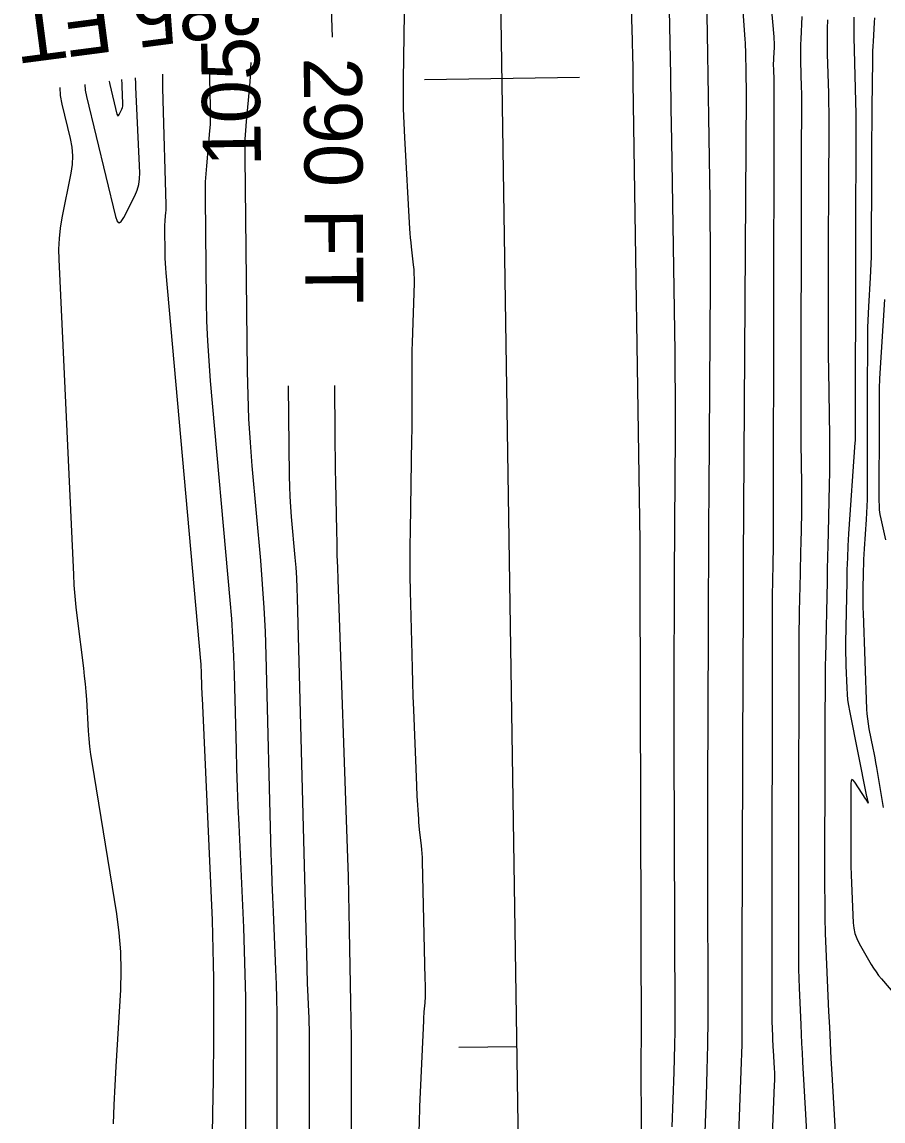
# Model space of a CAD drawing. Extents: x 1768942 to 1774819, y 723037 to 732099.
# Drawn here: x 1770772.9 to 1770861.8, y 724629.5 to 724743.1 of the extents above; entities that cross this region are included whole.
import ezdxf

# ---------------------------------------------------------------- set-up
doc = ezdxf.new("R2010")
doc.units = 0
for name, color, linetype in [('R_Contour Annot', 7, 'Continuous'), ('R_Contours', 7, 'Continuous'), ('R_Horz Alg', 7, 'Continuous'), ('R_Horz Alg Annot', 7, 'Continuous')]:
    doc.layers.add(name, color=color, linetype=linetype)

msp = doc.modelspace()

# ---------------------------------------------------------------- linework, layer by layer
at = {"layer": 'R_Contours'}
for points in [[(1770844.77, 724779.86), (1770847.51, 724741.26), (1770847.54, 724740.9), (1770847.56, 724740.53), (1770847.57, 724740.16), (1770847.58, 724739.79), (1770847.61, 724737.96), (1770847.62, 724737.76), (1770847.62, 724737.56), (1770847.62, 724737.37), (1770847.63, 724737.17), (1770847.64, 724736.38), (1770847.64, 724736.18), (1770847.64, 724735.98), (1770847.64, 724735.79), (1770847.64, 724735.59), (1770847.41, 724698.11), (1770847.38, 724692.78), (1770847.35, 724687.45), (1770847.33, 724682.11), (1770847.31, 724676.78), (1770847.2, 724646.63), (1770847.2, 724645.71), (1770847.2, 724644.79), (1770847.2, 724643.87), (1770847.2, 724642.95), (1770847.21, 724639.28), (1770847.21, 724638.36), (1770847.2, 724637.44), (1770847.18, 724636.53), (1770847.15, 724635.61), (1770846.14, 724608.57)], [(1770849.86, 724615.06), (1770850.59, 724633.3), (1770850.61, 724633.72), (1770850.61, 724634.14), (1770850.6, 724634.55), (1770850.58, 724634.97), (1770850.47, 724636.88), (1770850.45, 724637.18), (1770850.44, 724637.49), (1770850.42, 724637.79), (1770850.41, 724638.1), (1770850.36, 724639.32), (1770850.34, 724639.62), (1770850.34, 724639.93), (1770850.33, 724640.23), (1770850.33, 724640.54), (1770850.34, 724642.64), (1770850.34, 724643.1), (1770850.34, 724643.55), (1770850.34, 724644), (1770850.34, 724644.45), (1770850.38, 724684.06), (1770850.38, 724684.4), (1770850.39, 724684.75), (1770850.39, 724685.1), (1770850.4, 724685.45), (1770850.43, 724686.95), (1770850.44, 724687.24), (1770850.44, 724687.53), (1770850.45, 724687.82), (1770850.46, 724688.12), (1770850.48, 724689.29), (1770850.49, 724689.58), (1770850.49, 724689.87), (1770850.49, 724690.16), (1770850.49, 724690.46), (1770850.47, 724692.05), (1770850.46, 724692.41), (1770850.46, 724692.77), (1770850.46, 724693.13), (1770850.46, 724693.49), (1770850.53, 724732.48), (1770850.53, 724732.87), (1770850.53, 724733.26), (1770850.53, 724733.65), (1770850.54, 724734.04), (1770850.55, 724735.78), (1770850.55, 724736.08), (1770850.54, 724736.38), (1770850.54, 724736.68), (1770850.53, 724736.98), (1770850.5, 724738.24), (1770850.49, 724738.52), (1770850.49, 724738.79), (1770850.5, 724739.06), (1770850.51, 724739.34), (1770850.56, 724740.43), (1770850.56, 724740.7), (1770850.56, 724740.97), (1770850.55, 724741.24), (1770850.53, 724741.52), (1770847.14, 724779.89)], [(1770843.13, 724620.91), (1770843.55, 724632.15), (1770843.64, 724634.79), (1770843.69, 724637.42), (1770843.73, 724640.06), (1770843.73, 724642.69), (1770843.7, 724653.23), (1770843.69, 724655.86), (1770843.69, 724658.5), (1770843.69, 724661.13), (1770843.7, 724663.77), (1770843.76, 724680.19), (1770843.77, 724683.81), (1770843.79, 724687.42), (1770843.81, 724691.04), (1770843.83, 724694.65), (1770843.96, 724716.03), (1770843.97, 724718.18), (1770843.97, 724720.33), (1770843.95, 724722.49), (1770843.92, 724724.64), (1770843.79, 724733.25), (1770843.76, 724735.41), (1770843.73, 724737.56), (1770843.69, 724739.71), (1770843.65, 724741.86), (1770843.17, 724767.24)], [(1770835.26, 724760.92), (1770835.87, 724741.19), (1770835.88, 724740.82), (1770835.89, 724740.46), (1770835.9, 724740.1), (1770835.91, 724739.73), (1770835.94, 724738.27), (1770835.94, 724737.91), (1770835.95, 724737.55), (1770835.95, 724737.18), (1770835.96, 724736.82), (1770836.67, 724689.45), (1770836.67, 724689.24), (1770836.68, 724689.03), (1770836.68, 724688.82), (1770836.68, 724688.62), (1770836.67, 724687.74), (1770836.67, 724687.56), (1770836.67, 724687.37), (1770836.67, 724687.19), (1770836.67, 724687.01), (1770836.66, 724686.28), (1770836.66, 724686.1), (1770836.66, 724685.91), (1770836.66, 724685.73), (1770836.66, 724685.55), (1770836.81, 724637.51), (1770836.81, 724637.44), (1770836.81, 724637.37), (1770836.81, 724637.3), (1770836.8, 724637.23), (1770836.79, 724636.96), (1770836.79, 724636.89), (1770836.79, 724636.82), (1770836.79, 724636.75), (1770836.79, 724636.68), (1770836.95, 724590.56)], [(1770804.96, 724741.5), (1770804.71, 724748.47)], [(1770839.71, 724744.32), (1770839.77, 724740.93), (1770839.83, 724737.55), (1770839.89, 724734.17), (1770839.94, 724730.79), (1770840.27, 724709), (1770840.3, 724706.84), (1770840.31, 724704.68), (1770840.31, 724702.52), (1770840.31, 724700.36), (1770840.25, 724691.19), (1770840.24, 724689.3), (1770840.23, 724687.4), (1770840.22, 724685.5), (1770840.21, 724683.6), (1770840.19, 724676), (1770840.18, 724674.1), (1770840.18, 724672.21), (1770840.18, 724670.31), (1770840.18, 724668.41), (1770840.27, 724640.22), (1770840.27, 724638.81), (1770840.25, 724637.4), (1770840.22, 724635.99), (1770840.17, 724634.58), (1770839.96, 724628.94)], [(1770813.9, 724628.27), (1770813.93, 724629.66), (1770813.94, 724630), (1770813.95, 724630.35), (1770813.96, 724630.7), (1770813.97, 724631.04), (1770814.36, 724639.91), (1770814.37, 724640.14), (1770814.39, 724640.37), (1770814.4, 724640.6), (1770814.42, 724640.82), (1770814.5, 724641.77), (1770814.52, 724641.98), (1770814.53, 724642.18), (1770814.53, 724642.39), (1770814.53, 724642.59), (1770814.53, 724643.41), (1770814.53, 724643.61), (1770814.53, 724643.82), (1770814.52, 724644.02), (1770814.52, 724644.23), (1770814.24, 724656.37), (1770814.23, 724656.78), (1770814.21, 724657.18), (1770814.17, 724657.58), (1770814.13, 724657.98), (1770813.94, 724659.64), (1770813.9, 724660.02), (1770813.87, 724660.4), (1770813.84, 724660.78), (1770813.81, 724661.16), (1770813.71, 724662.68), (1770813.69, 724663.07), (1770813.67, 724663.45), (1770813.65, 724663.83), (1770813.64, 724664.21), (1770813.34, 724672.01), (1770813.28, 724673.44), (1770813.24, 724674.87), (1770813.19, 724676.29), (1770813.16, 724677.72), (1770813, 724684.27), (1770812.97, 724685.83), (1770812.96, 724687.4), (1770812.96, 724688.97), (1770812.98, 724690.54), (1770813.15, 724700.05), (1770813.16, 724700.87), (1770813.17, 724701.7), (1770813.17, 724702.52), (1770813.17, 724703.35), (1770813.16, 724706.65), (1770813.16, 724707.48), (1770813.17, 724708.3), (1770813.18, 724709.13), (1770813.2, 724709.96), (1770813.4, 724716.09), (1770813.4, 724716.56), (1770813.39, 724717.03), (1770813.36, 724717.49), (1770813.32, 724717.96), (1770813.1, 724719.83), (1770813.05, 724720.29), (1770813, 724720.76), (1770812.97, 724721.23), (1770812.94, 724721.7), (1770812.4, 724731.13), (1770812.33, 724732.61), (1770812.29, 724734.1), (1770812.27, 724735.58), (1770812.28, 724737.07), (1770812.37, 724743.93)], [(1770853.39, 724743.61), (1770853.28, 724741.3), (1770853.26, 724740.73), (1770853.25, 724740.15), (1770853.25, 724739.57), (1770853.26, 724739), (1770853.34, 724736.34), (1770853.35, 724735.7), (1770853.36, 724735.07), (1770853.37, 724734.43), (1770853.36, 724733.8), (1770853.34, 724730.13), (1770853.34, 724729.3), (1770853.34, 724728.48), (1770853.33, 724727.66), (1770853.33, 724726.83), (1770853.29, 724703.38), (1770853.29, 724702.43), (1770853.29, 724701.47), (1770853.3, 724700.51), (1770853.31, 724699.56), (1770853.37, 724695.37), (1770853.38, 724694.6), (1770853.38, 724693.83), (1770853.37, 724693.06), (1770853.36, 724692.28), (1770853.29, 724689.2), (1770853.27, 724688.43), (1770853.25, 724687.66), (1770853.23, 724686.88), (1770853.22, 724686.11), (1770853.13, 724682.16), (1770853.11, 724681.24), (1770853.1, 724680.32), (1770853.09, 724679.41), (1770853.09, 724678.49), (1770853.07, 724659.5), (1770853.07, 724658.07), (1770853.06, 724656.65), (1770853.06, 724655.22), (1770853.06, 724653.79), (1770853.04, 724647.16), (1770853.04, 724646.2), (1770853.06, 724645.24), (1770853.08, 724644.28), (1770853.12, 724643.32), (1770853.29, 724639.48), (1770853.33, 724638.52), (1770853.38, 724637.56), (1770853.43, 724636.6), (1770853.48, 724635.64), (1770853.82, 724629.63), (1770853.88, 724628.31)], [(1770856.06, 724743.27), (1770856.03, 724742.39), (1770856.01, 724741.51), (1770856.01, 724740.63), (1770856.03, 724739.75), (1770856.14, 724735.69), (1770856.16, 724734.72), (1770856.18, 724733.75), (1770856.18, 724732.78), (1770856.18, 724731.81), (1770856.15, 724726.21), (1770856.14, 724724.95), (1770856.14, 724723.7), (1770856.13, 724722.44), (1770856.13, 724721.18), (1770856.12, 724713.27), (1770856.12, 724711.72), (1770856.12, 724710.17), (1770856.13, 724708.62), (1770856.15, 724707.07), (1770856.25, 724700.28), (1770856.26, 724699.03), (1770856.26, 724697.78), (1770856.25, 724696.53), (1770856.23, 724695.28), (1770856.11, 724690.28), (1770856.08, 724689.03), (1770856.06, 724687.78), (1770856.03, 724686.53), (1770856, 724685.28), (1770855.83, 724677.43), (1770855.82, 724676.67), (1770855.81, 724675.9), (1770855.8, 724675.13), (1770855.8, 724674.36), (1770855.79, 724671.28), (1770855.79, 724670.51), (1770855.79, 724669.75), (1770855.79, 724668.98), (1770855.79, 724668.21), (1770855.75, 724653.78), (1770855.76, 724652.17), (1770855.78, 724650.55), (1770855.82, 724648.93), (1770855.88, 724647.32), (1770856.16, 724640.86), (1770856.24, 724639.24), (1770856.31, 724637.62), (1770856.4, 724636.01), (1770856.49, 724634.4), (1770857.17, 724622.43)], [(1770858.77, 724743.56), (1770858.76, 724742.87), (1770858.76, 724742.19), (1770858.77, 724741.5), (1770858.99, 724733.53), (1770858.99, 724733.43), (1770858.99, 724733.32), (1770858.99, 724733.21), (1770858.99, 724733.11), (1770858.98, 724732.68), (1770858.98, 724732.57), (1770858.98, 724732.47), (1770858.98, 724732.36), (1770858.98, 724732.25), (1770858.94, 724720.48), (1770858.94, 724720.33), (1770858.94, 724720.17), (1770858.94, 724720.01), (1770858.94, 724719.86), (1770858.94, 724718.92), (1770858.94, 724718.88), (1770858.94, 724718.86), (1770858.94, 724718.65), (1770858.94, 724718.61), (1770858.94, 724718.58), (1770858.94, 724718.54), (1770858.94, 724718.5), (1770858.91, 724701.53), (1770858.91, 724701.37), (1770858.91, 724701.21), (1770858.91, 724701.06), (1770858.91, 724700.9), (1770858.91, 724700.27), (1770858.9, 724700.11), (1770858.9, 724699.95), (1770858.89, 724699.8), (1770858.88, 724699.64), (1770858.23, 724690.18), (1770858.16, 724688.94), (1770858.1, 724687.7), (1770858.05, 724686.47), (1770858.03, 724685.23), (1770857.92, 724678.98), (1770857.92, 724678.38), (1770857.92, 724677.79), (1770857.93, 724677.2), (1770857.95, 724676.61), (1770858.04, 724674.24), (1770858.07, 724673.65), (1770858.13, 724673.06), (1770858.21, 724672.48), (1770858.31, 724671.9), (1770860.09, 724663.06), (1770860.1, 724663.04), (1770860.1, 724663.02), (1770860.1, 724663), (1770860.11, 724662.99), (1770860.12, 724662.91), (1770860.12, 724662.89), (1770860.13, 724662.88), (1770860.13, 724662.86), (1770860.13, 724662.84), (1770860.24, 724662.42), (1770860.25, 724662.38), (1770860.25, 724662.37), (1770860.24, 724662.38), (1770860.22, 724662.42), (1770860.11, 724662.61), (1770860.09, 724662.66), (1770860.06, 724662.71), (1770860.03, 724662.75), (1770860, 724662.8), (1770858.87, 724664.53), (1770858.7, 724664.75), (1770858.57, 724664.81), (1770858.5, 724664.69), (1770858.47, 724664.41), (1770858.45, 724657.6), (1770858.46, 724656.73), (1770858.47, 724655.86), (1770858.49, 724654.99), (1770858.53, 724654.12), (1770858.7, 724650.03), (1770858.76, 724649.47), (1770858.88, 724648.92), (1770859.07, 724648.4), (1770859.32, 724647.89), (1770860.57, 724645.71), (1770860.81, 724645.32), (1770861.06, 724644.94), (1770861.33, 724644.57), (1770861.62, 724644.22), (1770862.99, 724642.61)], [(1770860.9, 724743.49), (1770860.88, 724743), (1770860.76, 724741.04), (1770860.73, 724740.55), (1770860.71, 724740.06), (1770860.7, 724739.56), (1770860.69, 724739.07), (1770860.63, 724734.21), (1770860.61, 724733.24), (1770860.61, 724732.27), (1770860.6, 724731.29), (1770860.6, 724730.32), (1770860.58, 724725.31), (1770860.58, 724724.58), (1770860.58, 724723.86), (1770860.57, 724723.14), (1770860.57, 724722.42), (1770860.56, 724719.54), (1770860.55, 724718.81), (1770860.53, 724718.09), (1770860.5, 724717.37), (1770860.46, 724716.65), (1770860.27, 724713.69), (1770860.23, 724712.96), (1770860.2, 724712.23), (1770860.18, 724711.49), (1770860.18, 724710.76), (1770860.16, 724704.22), (1770860.16, 724703.1), (1770860.16, 724701.99), (1770860.16, 724700.87), (1770860.15, 724699.75), (1770860.14, 724694.41), (1770860.13, 724693.73), (1770860.11, 724693.04), (1770860.08, 724692.35), (1770860.04, 724691.67), (1770859.83, 724688.66), (1770859.8, 724688.1), (1770859.77, 724687.55), (1770859.75, 724686.99), (1770859.74, 724686.44), (1770859.7, 724684.22), (1770859.7, 724683.66), (1770859.7, 724683.11), (1770859.71, 724682.55), (1770859.73, 724682), (1770860.09, 724672.1), (1770860.12, 724671.59), (1770860.17, 724671.08), (1770860.24, 724670.58), (1770860.33, 724670.07), (1770860.73, 724668.07), (1770860.83, 724667.57), (1770860.93, 724667.06), (1770861.02, 724666.56), (1770861.11, 724666.06), (1770861.8, 724661.94)], [(1770799.24, 724627.33), (1770799.24, 724639.21), (1770799.23, 724640.7), (1770799.21, 724642.19), (1770799.16, 724643.69), (1770799.1, 724645.18), (1770798.84, 724651.15), (1770798.77, 724652.65), (1770798.72, 724654.14), (1770798.67, 724655.63), (1770798.62, 724657.13), (1770798.1, 724677.67), (1770798.02, 724680.12), (1770797.89, 724682.56), (1770797.73, 724685.01), (1770797.54, 724687.44), (1770796.66, 724697.2), (1770796.47, 724699.64), (1770796.32, 724702.08), (1770796.22, 724704.52), (1770796.17, 724706.97), (1770795.92, 724729.08), (1770795.92, 724730.01), (1770795.94, 724730.94), (1770795.99, 724731.86), (1770796.07, 724732.79), (1770796.41, 724736.48), (1770796.48, 724737.41), (1770796.52, 724738.33), (1770796.54, 724738.86)], [(1770792.38, 724618.38), (1770792.63, 724632.17), (1770792.65, 724633.68), (1770792.67, 724635.19), (1770792.68, 724636.7), (1770792.68, 724638.21), (1770792.68, 724644.25), (1770792.67, 724645.75), (1770792.64, 724647.26), (1770792.6, 724648.77), (1770792.54, 724650.28), (1770791.51, 724673.23), (1770791.49, 724673.54), (1770791.48, 724673.86), (1770791.47, 724674.18), (1770791.46, 724674.5), (1770791.43, 724675.77), (1770791.42, 724676.09), (1770791.4, 724676.41), (1770791.38, 724676.73), (1770791.36, 724677.05), (1770787.77, 724717.14), (1770787.73, 724717.64), (1770787.7, 724718.14), (1770787.68, 724718.65), (1770787.67, 724719.15), (1770787.64, 724721.77), (1770787.64, 724721.97), (1770787.65, 724722.18), (1770787.66, 724722.38), (1770787.67, 724722.58), (1770787.75, 724723.38), (1770787.76, 724723.58), (1770787.77, 724723.78), (1770787.77, 724723.98), (1770787.77, 724724.18), (1770787.45, 724734.99), (1770787.43, 724736.26), (1770787.43, 724737.54), (1770787.43, 724737.67)], [(1770792.24, 724738.3), (1770792.24, 724738.13), (1770792.24, 724737.66), (1770792.24, 724737.2), (1770792.33, 724734.35), (1770792.34, 724733.72), (1770792.33, 724733.09), (1770792.3, 724732.46), (1770792.25, 724731.83), (1770791.92, 724728.19), (1770791.85, 724727.37), (1770791.81, 724726.56), (1770791.79, 724725.74), (1770791.79, 724724.92), (1770791.91, 724714.22), (1770791.95, 724712.16), (1770792.04, 724710.11), (1770792.16, 724708.06), (1770792.32, 724706.01), (1770794.35, 724683.35), (1770794.5, 724681.42), (1770794.63, 724679.49), (1770794.73, 724677.55), (1770794.79, 724675.62), (1770794.99, 724667.87), (1770795.04, 724665.94), (1770795.11, 724664), (1770795.18, 724662.07), (1770795.26, 724660.13), (1770795.74, 724649.55), (1770795.84, 724647.14), (1770795.9, 724644.73), (1770795.95, 724642.32), (1770795.96, 724639.91), (1770795.97, 724615.46)], [(1770779.37, 724736.61), (1770779.41, 724736.01), (1770779.53, 724735.37), (1770782.54, 724722.96), (1770782.71, 724722.5), (1770782.91, 724722.33), (1770783.14, 724722.45), (1770783.4, 724722.86), (1770784.53, 724725.11), (1770784.78, 724725.68), (1770784.94, 724726.26), (1770785.03, 724726.86), (1770785.04, 724727.48), (1770784.65, 724736.32), (1770784.63, 724736.77), (1770784.6, 724737.22), (1770784.6, 724737.3)], [(1770781.91, 724736.95), (1770781.9, 724736.92), (1770781.92, 724736.77), (1770781.94, 724736.61), (1770782.69, 724733.53), (1770782.73, 724733.42), (1770782.78, 724733.38), (1770782.84, 724733.41), (1770782.91, 724733.51), (1770783.18, 724734.07), (1770783.25, 724734.21), (1770783.29, 724734.35), (1770783.31, 724734.5), (1770783.31, 724734.65), (1770783.23, 724736.38), (1770783.22, 724736.72), (1770783.2, 724737.06), (1770783.2, 724737.11)], [(1770776.78, 724736.28), (1770776.83, 724735.47), (1770777, 724734.58), (1770777.86, 724731.02), (1770778.03, 724730.13), (1770778.1, 724729.24), (1770778.07, 724728.35), (1770777.94, 724727.45), (1770777.01, 724722.83), (1770776.82, 724721.76), (1770776.71, 724720.68), (1770776.66, 724719.6), (1770776.68, 724718.51), (1770778.19, 724686.01), (1770778.25, 724684.88), (1770778.34, 724683.74), (1770778.44, 724682.61), (1770778.58, 724681.48), (1770779.23, 724676.31), (1770779.32, 724675.5), (1770779.41, 724674.7), (1770779.47, 724673.89), (1770779.53, 724673.08), (1770779.73, 724669.83), (1770779.79, 724669.02), (1770779.87, 724668.22), (1770779.97, 724667.41), (1770780.09, 724666.61), (1770782.64, 724650.95), (1770782.9, 724649), (1770783.05, 724647.03), (1770783.1, 724645.07), (1770783.04, 724643.09), (1770782.57, 724635.19), (1770782.46, 724633.21), (1770782.37, 724631.23), (1770782.31, 724629.25)], [(1770862.07, 724689.56), (1770861.59, 724691.74), (1770861.5, 724692.2), (1770861.43, 724692.66), (1770861.4, 724693.13), (1770861.38, 724693.6), (1770861.41, 724702.06), (1770861.41, 724702.41), (1770861.41, 724702.76), (1770861.41, 724703.11), (1770861.41, 724703.45), (1770861.41, 724704.85), (1770861.42, 724705.19), (1770861.42, 724705.54), (1770861.44, 724705.89), (1770861.46, 724706.24), (1770861.98, 724714.4)], [(1770800.37, 724705.47), (1770800.48, 724696.15), (1770800.5, 724695.09), (1770800.54, 724694.04), (1770800.61, 724692.99), (1770800.69, 724691.94), (1770801.06, 724687.74), (1770801.15, 724686.7), (1770801.22, 724685.64), (1770801.27, 724684.59), (1770801.31, 724683.54), (1770802.28, 724645.43), (1770802.3, 724644.85), (1770802.32, 724644.28), (1770802.34, 724643.7), (1770802.36, 724643.12), (1770802.47, 724640.81), (1770802.49, 724640.24), (1770802.51, 724639.66), (1770802.52, 724639.08), (1770802.52, 724638.5), (1770802.52, 724633.92), (1770802.52, 724632.96), (1770802.52, 724632), (1770802.53, 724631.04), (1770802.53, 724630.09), (1770802.68, 724593.34)], [(1770806.94, 724606.63), (1770806.91, 724634.33), (1770806.9, 724636.19), (1770806.89, 724638.06), (1770806.87, 724639.92), (1770806.84, 724641.79), (1770806.71, 724649.25), (1770806.68, 724651.12), (1770806.63, 724652.98), (1770806.58, 724654.85), (1770806.52, 724656.71), (1770805.52, 724685.47), (1770805.48, 724686.73), (1770805.44, 724687.99), (1770805.41, 724689.25), (1770805.38, 724690.51), (1770805.28, 724695.55), (1770805.25, 724696.8), (1770805.24, 724698.06), (1770805.22, 724699.32), (1770805.22, 724700.58), (1770805.2, 724705.5)]]:
    msp.add_lwpolyline(points, dxfattribs=at)
at = {"layer": 'R_Horz Alg'}
msp.add_line((1770830.14, 724237.3), (1770821.12, 724822.68), dxfattribs=at)
msp.add_line((1770830.14, 724237.3), (1770821.12, 724822.68), dxfattribs=at)
for points in [[(1770814.43, 724737.12), (1770830.43, 724737.36)], [(1770817.98, 724637.16), (1770823.97, 724637.25)]]:
    msp.add_lwpolyline(points, dxfattribs=at)

# ---------------------------------------------------------------- texts
at = {"layer": 'R_Contour Annot'}
for s, rotation, p in [('285 FT', 187.45, (1770797.21, 724748.02)), ('290 FT', 270.3874, (1770801.97, 724739.38))]:
    msp.add_text(s, height=6, rotation=rotation, dxfattribs=at).set_placement(p)
at = {"layer": 'R_Horz Alg Annot'}
msp.add_text('105', height=6, rotation=90.8827, dxfattribs=at).set_placement((1770797.57, 724728.17))

doc.saveas('drawing.dxf')
